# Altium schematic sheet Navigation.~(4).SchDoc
size A
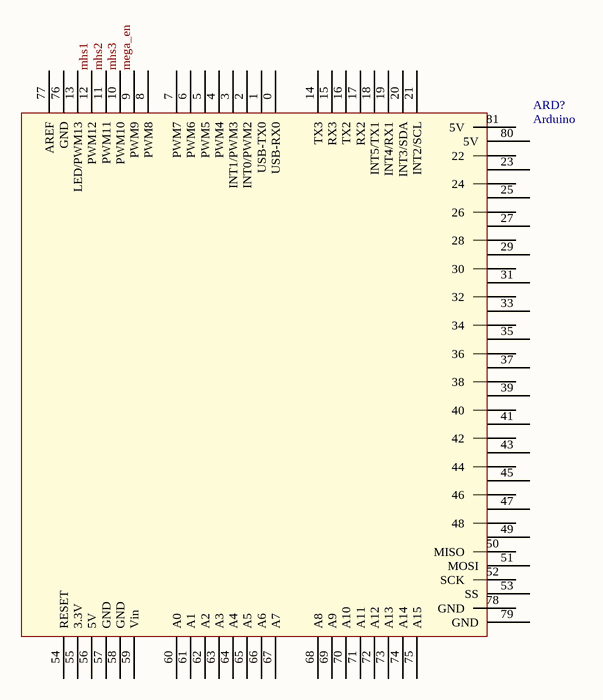
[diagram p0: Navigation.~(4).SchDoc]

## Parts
ARD?  Arduino  [Arduino]

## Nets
mega_en: ARD?.9(PWM9)
mhs1: ARD?.12(PWM12)
mhs2: ARD?.11(PWM11)
mhs3: ARD?.10(PWM10)

Not connected (* = marked no-connect by the designer): ARD? 0(USB-RX0) 1(USB-TX0) 2(INT0/PWM2) 3(INT1/PWM3) 4(PWM4) 5(PWM5) 6(PWM6) 7(PWM7) 8(PWM8) 13(LED/PWM13) 14(TX3) 15(RX3) 16(TX2) 17(RX2) 18(INT5/TX1) 19(INT4/RX1) 20(INT3/SDA) 21(INT2/SCL) 22 23 24 25 26 27 28 29 30 31 32 33 34 35 36 37 38 39 40 41 42 43 44 45 46 47 48 49 50(MISO) 51(MOSI) 52(SCK) 53(SS) 54(RESET) 55(3.3V) 56(5V) 57(GND) 58(GND) 59(Vin) 60(A0) 61(A1) 62(A2) 63(A3) 64(A4) 65(A5) 66(A6) 67(A7) 68(A8) 69(A9) 70(A10) 71(A11) 72(A12) 73(A13) 74(A14) 75(A15) 76(GND) 77(AREF) 78(GND) 79(GND) 80(5V) 81(5V)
